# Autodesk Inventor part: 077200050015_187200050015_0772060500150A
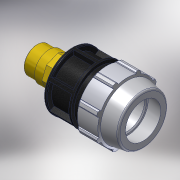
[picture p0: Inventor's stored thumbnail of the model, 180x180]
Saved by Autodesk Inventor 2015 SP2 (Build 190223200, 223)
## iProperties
Created: 2017-02
Part Number: 077200050015_187200050015_0772060500150A
Material: PVC-Piping
Description: PLASSON MALE ADAPTOR INTEGRAL BRASS THREAD 50-1.1/2"
Document SubType Name: Modeling
Designer: KIM
Mass: 92.6774 g
Surface Area: 199.44 cm^2
Volume: 66.1981 cm^3
Density: 1.4 g/cm^3
Appearance: PTFE
Author: KIM
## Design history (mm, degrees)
derived "07720.ipt"
feature "Solid1::07720.ipt"
tag "TaggingFeature1"
body "Solid1"
other parameters: "d4" = 24.57143, "d5" = 24.57143, "d7" = 96, "d8" = 72, "d9" = 24.57143, "d11" = 4.91429, "d12" = 76.8, "d13" = 120 deg, "d14" = 75, "d15" = 10 deg, "d16" = 86.4, "d18" = 2.5, "d19" = 35 deg, "d20" = 17.5 deg, "d21" = 89.28, "d23" = 0, "d25" = 360 deg, "d27" = 1.92, "d34" = 4.8, "d36" = 0, "d42" = 34.4, "d43" = 2.88, "d46" = 1.5, "d49" = 106, "d51" = 172, "d53" = 1, "d55" = 360 deg, "d59" = 34.4, "d60" = 47.803, "d61" = 52.5833, "d62" = 22, "d63" = 57.33333, "d64" = 33.4621, "d65" = 172, "d66" = 19.54406, "d67" = 0, "d68" = 1, "d71" = 30 deg, "d72" = 43.0227, "E_" = 96, "H_" = 172, "l_" = 106, "l_2" = 22, "R_" = 47.803, "d73" = 32.57343
